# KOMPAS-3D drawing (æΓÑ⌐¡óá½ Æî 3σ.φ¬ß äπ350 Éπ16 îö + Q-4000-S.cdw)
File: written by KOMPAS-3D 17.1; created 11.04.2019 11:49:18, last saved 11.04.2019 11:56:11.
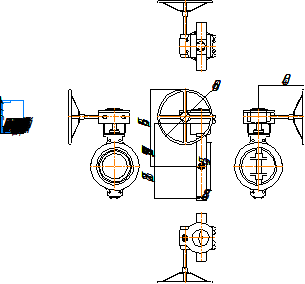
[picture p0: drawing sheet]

Sheet 1: A4, portrait

Title block, sheet 1: name: Стейнвал ТМ 3х.экс / Ду350 Ру16 МФ + Q-4000-S; material: Внимание! Данный продукт является объектом авторского права ООО «Торговый Дом АДЛ». / Запрещается изменение, копирование, распространение / (в том числе путем копирования на другие сайты и ресурсы в Интернете) / или любое иное использование информации и объектов без предварительного / согласия правообладателя (ООО «Торговый Дом АДЛ»).; mass: 152,1; sheets: 1; organisation: ООО "Торговый дом АДЛ"; sheet format: A4; stored path: \\adlc.lan\data\АДЛ_ПКД\3D-модели\ADL production\Дисковые поворотные затворы СТЕЙНВАЛ\Трехэксцентриковый\Стейнвал м-ф\С редуктором\KOMPAS 2D\Стейнвал ТМ 3х.экс  Ду350 Ру16 МФ + Q-4000-S.cdw

Views: Вид 1, Проекционный вид 2, Проекционный вид 3, Проекционный вид 4, Проекционный вид 5
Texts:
  user
Dimensions and other numbers on the sheet: 435; 88; 390,95±0,7; 695,45; 287,25; 500; 408; 1:1; 1; 152,1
